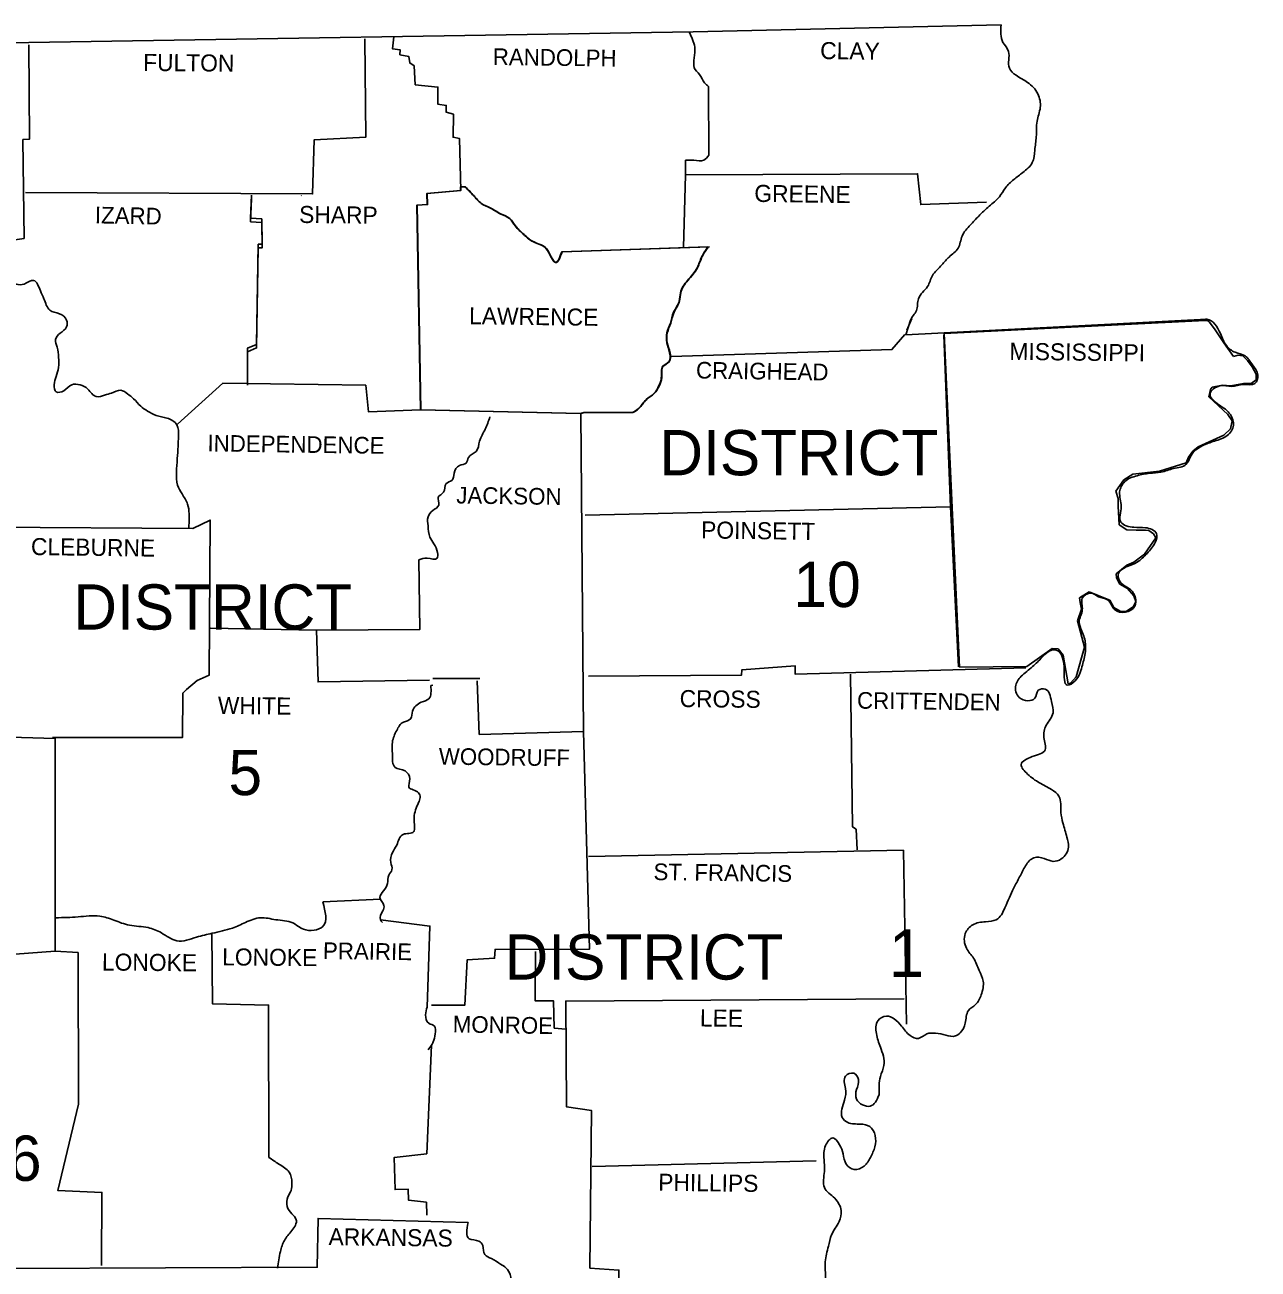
# Model space of a CAD drawing. Extents: x -42408 to 34530, y -43140 to 20491.
# Drawn here: x 3155 to 4711, y -34581 to -33011 of the extents above; entities that cross this region are included whole.
import ezdxf

# ---------------------------------------------------------------- set-up
doc = ezdxf.new("R2010")
doc.units = 0
for name, color, linetype in [('1', 7, 'Continuous'), ('2', 7, 'Continuous'), ('3', 7, 'Continuous'), ('S_MISC_BOUNDARY', 7, 'Continuous')]:
    doc.layers.add(name, color=color, linetype=linetype)

msp = doc.modelspace()

# ---------------------------------------------------------------- linework, layer by layer
at = {"layer": '1'}
for p, q in [((3988.7, -33181.7), (3988.7, -33200.2)), ((3710.3, -33215.2), (3704.6, -33215.4)), ((4016.7, -33290.9), (3832.4, -33297.3)), ((3985.1, -33292.3), (3986, -33291.4)), ((3825, -33310.9), (3829.8, -33306.1)), ((4266.5, -33401.9), (4272.5, -33383.4)), ((4268, -33395.9), (4274, -33381.4)), ((4315, -33400.1), (4644.3, -33383.9)), ((4644.3, -33383.9), (4647.2, -33383.8)), ((4647.2, -33383.8), (4649.5, -33385.4)), ((4649.5, -33385.4), (4655.9, -33394.5)), ((4334.5, -33821.1), (4315, -33400.1)), ((4655.9, -33394.5), (4667.9, -33411.9)), ((4667.9, -33411.9), (4679.9, -33429.2)), ((4679.9, -33429.2), (4685.9, -33427.5)), ((4685.9, -33427.5), (4692, -33428.6)), ((4692, -33428.6), (4697.6, -33434.2)), ((4697.6, -33434.2), (4703.8, -33442.5)), ((4703.8, -33442.5), (4708.6, -33451.8)), ((4708.6, -33451.8), (4708.7, -33458.8)), ((4653.2, -33468.1), (4651.1, -33471)), ((4666, -33465.3), (4653.2, -33468.1)), ((4676.7, -33466.5), (4666, -33465.3)), ((4692.8, -33463.3), (4676.7, -33466.5)), ((4702.5, -33463.2), (4692.8, -33463.3)), ((4708.7, -33458.8), (4702.5, -33463.2)), ((4651.1, -33471), (4648.8, -33480.2)), ((4648.8, -33480.2), (4672.8, -33502.5)), ((4672.8, -33502.5), (4678.4, -33510.7)), ((4678.4, -33510.7), (4676.2, -33520.4)), ((4668, -33528.6), (4635.4, -33543.1)), ((4676.2, -33520.4), (4668, -33528.6)), ((4635.4, -33543.1), (4628.9, -33548.6)), ((4623.1, -33556.2), (4620.5, -33563.5)), ((4628.9, -33548.6), (4623.1, -33556.2)), ((4552.9, -33577.8), (4541.5, -33585.1)), ((4586.5, -33574.2), (4552.9, -33577.8)), ((4620.5, -33563.5), (4586.5, -33574.2)), ((4541.5, -33585.1), (4531.6, -33599.2)), ((4531.6, -33599.2), (4534.7, -33608.3)), ((4534.7, -33608.3), (4534.7, -33618)), ((4534.7, -33618), (4535.6, -33641.9)), ((4535.6, -33641.9), (4545.6, -33647.9)), ((4545.6, -33647.9), (4557.4, -33648.3)), ((4557.4, -33648.3), (4569.1, -33648.6)), ((4569.1, -33648.6), (4573.4, -33648.8)), ((4573.4, -33648.8), (4578.9, -33652.9)), ((4578.9, -33652.9), (4582.2, -33658.3)), ((4582.2, -33658.3), (4567.8, -33678.8)), ((4567.8, -33678.8), (4554.3, -33689)), ((4545.5, -33692.7), (4532.1, -33703.6)), ((4532.1, -33703.6), (4532.5, -33708.7)), ((4554.3, -33689), (4545.5, -33692.7)), ((4532.5, -33708.7), (4536.7, -33716.6)), ((4536.7, -33716.6), (4546.5, -33722)), ((4497.8, -33726.2), (4485.9, -33733.9)), ((4485.9, -33733.9), (4486.5, -33739.7)), ((4509.2, -33730.9), (4497.8, -33726.2)), ((4524, -33736.9), (4509.2, -33730.9)), ((4546.5, -33722), (4554.1, -33731.2)), ((4554.1, -33731.2), (4556.7, -33738.4)), ((4488.2, -33748.2), (4483.2, -33762.7)), ((4486.5, -33739.7), (4488.2, -33748.2)), ((4528.9, -33745.9), (4524, -33736.9)), ((4537.7, -33750.9), (4528.9, -33745.9)), ((4544.9, -33750.6), (4537.7, -33750.9)), ((4553.8, -33744.8), (4544.9, -33750.6)), ((4556.7, -33738.4), (4553.8, -33744.8)), ((4483.2, -33762.7), (4492, -33796)), ((4451.3, -33797.6), (4419.2, -33820.5)), ((4458.6, -33798.1), (4451.3, -33797.6)), ((4465.1, -33806.2), (4458.6, -33798.1)), ((4492, -33796), (4481.5, -33833.4)), ((4471.3, -33842.5), (4465.1, -33806.2)), ((4419.2, -33820.5), (4334.5, -33821.1)), ((3669.7, -33835.5), (3729.3, -33835.5)), ((4474.2, -33841.5), (4471.3, -33842.5)), ((4481.5, -33833.4), (4474.2, -33841.5))]:
    msp.add_line(p, q, dxfattribs=at)
for points in [[(1640, -33034), (2449.6, -33034.5), (3160, -33033), (3998.2, -33019.9), (4386.7, -33010.9)], [(3584.1, -33028.4), (3585.1, -33152.6), (3520, -33156.1), (3518, -33224.2), (3156, -33222.2)], [(3620.6, -33025.8), (3618.7, -33041), (3628.7, -33042.5), (3628.2, -33048.5), (3639.7, -33051), (3640.7, -33059), (3646.2, -33062.5), (3647.7, -33086.5), (3676.2, -33089.5), (3676.2, -33111.1), (3686.7, -33112.6), (3686.7, -33121.1), (3695.8, -33123.6), (3695.3, -33152.6), (3703.3, -33154.1), (3705.3, -33219.7), (3662.7, -33223.7), (3663.2, -33237.7), (3650.2, -33238.2), (3654.7, -33496.6), (3856.5, -33501.1), (3860, -33902.6), (3728.3, -33906.1), (3725.8, -33838.5)], [(3160, -33036), (3161, -33155.1), (3152.5, -33155.6), (3154, -33280.3), (3119, -33285.3), (3122, -33318.8), (3134, -33334.4), (3133, -33373.9), (3064.9, -33376.4), (3062.4, -33437.5), (3000.3, -33439.5), (2997.3, -33513.6), (3000.8, -33519.6), (3002.3, -33637.8), (3109.5, -33644.8), (3108, -33908.6), (3193.1, -33911.1), (3193.1, -34179.5), (3126, -34184.5), (3121, -34243.6), (3008.3, -34244.1)], [(4017.7, -33088.5), (4018.2, -33175.1)], [(3986, -33291.9), (3988.7, -33200.2), (3988.7, -33200.2), (4281.5, -33198.7), (4285.5, -33237.7), (4368.2, -33234.7)], [(3704.6, -33215.4), (3704.8, -33219.7), (3662.2, -33223.7), (3662.7, -33237.7), (3649.7, -33238.2), (3654.2, -33496.6), (3856, -33501.1)], [(3440.9, -33225.7), (3439.9, -33254.7), (3453.9, -33255.8), (3454.4, -33287.8), (3449.4, -33287.8), (3447.4, -33414), (3435.9, -33419), (3435.9, -33461)], [(3440.9, -33230.2), (3439.9, -33259.3), (3453.9, -33260.3), (3454.4, -33292.3), (3449.4, -33292.3), (3447.4, -33418.5), (3435.9, -33423.5), (3435.9, -33465.5)], [(3503.5, -33226.7), (3504, -33226.2)], [(3832.9, -33297.3), (4018.7, -33290.8)], [(4016.7, -33291.3), (4016.7, -33290.9)], [(4266.5, -33401.9), (4646.5, -33382.4)], [(3971.1, -33429.5), (4249, -33420.5), (4265.5, -33401.4)], [(4314.6, -33402.4), (4323.1, -33619.2), (4333.1, -33821)], [(3347.8, -33514.6), (3404.9, -33463), (3585.1, -33465.5), (3588.6, -33499.1), (3654.2, -33496.6)], [(3856, -33501.1), (3860.5, -33500.1), (3921.6, -33500.1)], [(3922.1, -33500.1), (3861, -33500.1), (3856.5, -33501.1)], [(4323.1, -33619.2), (3862, -33629.7)], [(3109.5, -33644.8), (3366.8, -33646.3), (3388.9, -33635.8), (3387.4, -33831.5), (3372.3, -33838), (3358.8, -33849.5), (3354.3, -33854), (3353.8, -33910.1), (3190.1, -33910.1)], [(3652.2, -33685.8), (3653.2, -33773.9), (3523, -33774.4), (3389.4, -33771.9)], [(3523, -33774.4), (3525, -33840), (3665.7, -33837.5)], [(3866, -33832.5), (4059.2, -33831.5), (4059.7, -33824.5), (4126.8, -33819.5), (4126.8, -33830), (4418.2, -33822)], [(4196.9, -33830), (4199.4, -34022.8), (4203.9, -34025.8), (4205.4, -34051.8)], [(3669.7, -33844), (3667.2, -33844.5)], [(3860, -33902.6), (3867.5, -34177), (3748.3, -34177.5), (3747.8, -34188.5), (3713.3, -34190.5), (3710.3, -34247.6), (3668.2, -34247.6)], [(3866, -34060.3), (4263.5, -34052.3)], [(4263.5, -34052.3), (4267.5, -34271.6)], [(3531, -34117.4), (3603.6, -34113.9)], [(3603.6, -34139.9), (3666.2, -34147.9), (3662.7, -34250.1)], [(3390.9, -34156.5), (3391.9, -34246.1), (3462.5, -34247.6), (3463, -34439.8)], [(3193.1, -34179.5), (3222.1, -34181.5), (3222.6, -34372.7), (3196.6, -34481.4), (3252.2, -34483.9), (3251.7, -34576)], [(3799.4, -34180), (3798.9, -34242.1), (3821.9, -34242.1), (3822.9, -34276.6), (3837.5, -34278.1)], [(3866, -34686.2), (3905, -34683.7), (3904.5, -34582), (3868, -34579.5), (3870, -34380.8), (3838.5, -34376.2), (3837.5, -34242.6), (4264.5, -34239.6)], [(3668.2, -34298.1), (3662.2, -34435.3), (3621.2, -34439.8), (3622.2, -34480.4), (3638.7, -34479.9), (3639.2, -34493.9), (3661.7, -34496.4), (3662.2, -34512.9)], [(3871, -34451.3), (4153.4, -34444.3)], [(3714.3, -34521.9), (3525, -34516.9), (3524, -34578.5), (3141, -34580)]]:
    msp.add_lwpolyline(points, dxfattribs=at)
for points in [[(4386.7, -33010.9), (4389.2, -33033), (4396.2, -33044.5), (4397.2, -33065.5), (4405.7, -33074.5), (4420.2, -33083.5), (4433.2, -33098), (4436.2, -33115.1), (4432.2, -33132.6), (4431.2, -33152.1), (4429.2, -33169.1), (4426.2, -33184.7), (4414.2, -33197.2), (4402.7, -33206.2), (4392.2, -33216.7), (4384.7, -33227.7), (4371.7, -33239.7), (4358.6, -33252.2), (4348.1, -33263.3), (4337.6, -33277.3), (4332.6, -33292.8), (4321.1, -33303.8), (4312.1, -33313.8), (4300.1, -33327.3), (4294.1, -33340.9), (4282.5, -33356.4), (4280, -33371.4), (4272.5, -33383.4), (4272, -33385.4)], [(3993.3, -33020), (4000.2, -33039), (3999.7, -33052.5), (3999.7, -33065), (4006.2, -33073.5), (4012.7, -33084), (4017.7, -33088.5)], [(4018.2, -33175.1), (4011.7, -33181.7), (3999.2, -33181.7), (3988.7, -33181.7)], [(3832.4, -33297.3), (3824.4, -33310.8), (3816.9, -33300.3), (3811.4, -33291.8), (3794.9, -33283.8), (3784.4, -33275.3), (3773.9, -33264.8), (3766.4, -33255.2), (3754.8, -33249.2), (3741.8, -33241.7), (3730.8, -33236.2), (3721.3, -33226.7), (3710.3, -33215.2)], [(3710.8, -33215.2), (3721.8, -33226.7), (3731.3, -33236.2), (3742.3, -33241.7), (3755.3, -33249.2), (3766.9, -33255.2), (3774.4, -33264.8), (3784.9, -33275.3), (3795.4, -33283.8), (3811.9, -33291.8), (3817.4, -33300.3), (3824.9, -33310.8), (3832.9, -33297.3)], [(3921.6, -33500.1), (3929.1, -33495.1), (3939.1, -33483.6), (3948.6, -33476), (3955.1, -33466), (3958.1, -33456), (3960.1, -33441.5), (3967.6, -33436), (3968.6, -33424.5), (3965.1, -33412), (3965.1, -33399.4), (3969.6, -33387.4), (3973.6, -33373.4), (3980.6, -33359.4), (3982.1, -33348.9), (3991.2, -33333.4), (4003.2, -33317.3), (4009.2, -33303.3), (4016.7, -33291.3)], [(4017.2, -33291.3), (4009.7, -33303.3), (4003.7, -33317.3), (3991.7, -33333.4), (3982.6, -33348.9), (3981.1, -33359.4), (3974.1, -33373.4), (3970.1, -33387.4), (3965.6, -33399.4), (3965.6, -33412), (3969.1, -33424.5), (3968.1, -33436), (3960.6, -33441.5), (3958.6, -33456), (3955.6, -33466), (3949.1, -33476), (3939.6, -33483.6), (3929.6, -33495.1), (3922.1, -33500.1)], [(3134, -33334.4), (3154, -33337.9), (3166.1, -33333.4), (3174.6, -33346.4), (3179.1, -33356.4), (3186.6, -33370.9), (3198.6, -33375.4), (3207.6, -33383.4), (3207.6, -33391.9), (3199.6, -33399.9), (3193.6, -33408), (3195.6, -33417.5), (3197.6, -33430.5), (3197.6, -33443), (3194.6, -33454.5), (3192.1, -33465), (3194.6, -33474), (3204.1, -33472.5), (3214.1, -33465), (3224.6, -33465), (3234.6, -33470.5), (3245.2, -33480), (3255.7, -33478), (3264.2, -33475.5), (3276.2, -33472), (3284.7, -33476.5), (3292.2, -33482.6), (3301.2, -33492.1), (3309.7, -33498.1), (3320.8, -33503.6), (3334.3, -33507.1), (3346.8, -33515.6), (3348.8, -33530.1), (3348.3, -33542.6), (3347.3, -33558.2), (3346.3, -33575.2), (3347.8, -33591.7), (3353.3, -33602.7), (3360.3, -33615.7), (3362.3, -33627.7), (3361.8, -33646.8)], [(4641, -33382.9), (4646.5, -33382.4), (4663.6, -33400.4), (4671.1, -33415.5), (4682.1, -33424), (4694.6, -33428.5), (4704.1, -33440), (4710.6, -33452.5), (4707.1, -33463.5), (4693.1, -33464.5), (4677.6, -33467), (4662.6, -33466.5), (4650.5, -33476.5), (4661.6, -33490.1), (4676.1, -33502.6), (4680.1, -33516.1), (4672.1, -33529.1), (4656, -33536.1), (4640.5, -33542.1), (4626.5, -33554.1), (4620, -33565.7), (4604.5, -33570.7), (4588.5, -33575.2), (4574.4, -33576.7), (4558.4, -33579.7), (4542.9, -33587.2), (4536.4, -33600.2), (4538.4, -33618.7), (4537.9, -33638.3), (4554.4, -33644.8), (4568.9, -33645.3), (4582.9, -33652.8), (4581.4, -33663.8), (4570.9, -33677.8), (4558.4, -33688.8), (4545.9, -33694.3), (4534.4, -33704.8), (4538.4, -33715.4), (4548.9, -33722.4), (4556.4, -33733.9), (4555.4, -33744.4), (4543.4, -33751.9), (4530.4, -33748.9), (4520.9, -33736.4), (4509.8, -33732.4), (4500.3, -33727.9), (4489.3, -33734.4), (4489.3, -33748.9), (4485.3, -33764.4), (4488.8, -33775.9), (4493.3, -33792), (4492.8, -33804), (4488.8, -33821), (4480.3, -33838.5), (4470.3, -33844), (4466.3, -33825), (4464.3, -33809.5), (4458.3, -33800.5), (4450.3, -33800), (4439.8, -33807.5), (4428.2, -33819), (4413.7, -33831.5), (4405.2, -33844), (4409.7, -33859.6), (4420.7, -33863.6), (4429.2, -33860.6), (4433.7, -33850.5), (4442.3, -33849), (4450.3, -33864.6)], [(3741.8, -33505.6), (3735.8, -33521.1), (3728.8, -33536.1), (3724.3, -33549.1), (3714.8, -33556.7), (3711.8, -33563.7), (3703.3, -33566.7), (3696.8, -33576.7), (3693.8, -33585.7), (3686.7, -33589.7), (3683.2, -33600.7), (3676.7, -33606.7), (3677.2, -33616.7), (3669.7, -33623.7), (3663.7, -33631.8), (3663.7, -33642.8), (3666.2, -33657.3), (3671.2, -33665.8), (3675.7, -33676.8), (3675.2, -33683.8), (3662.7, -33683.8), (3652.2, -33685.8)], [(3667.2, -33844.5), (3664.7, -33861.1), (3655.2, -33865.6), (3644.2, -33876.6), (3641.7, -33886.6), (3632.7, -33890.6), (3624.2, -33901.1), (3618.7, -33915.6), (3618.7, -33930.7), (3622.2, -33947.7), (3634.7, -33952.2), (3640.7, -33962.2), (3639.7, -33972.7), (3651.7, -33979.7), (3653.7, -33985.7), (3651.7, -33992.2), (3646.2, -34010.8), (3646.7, -34023.3), (3645.7, -34028.8), (3632.2, -34032.3), (3624.2, -34045.8), (3618.7, -34055.3), (3616.7, -34067.8), (3618.2, -34076.8), (3614.2, -34083.9), (3612.7, -34094.4), (3607.6, -34103.4), (3603.1, -34111.9), (3608.1, -34121.9), (3606.6, -34128.9), (3603.6, -34139.9), (3606.1, -34143.4)], [(4450.3, -33864.6), (4452.3, -33879.1), (4443.8, -33894.6), (4440.8, -33910.1), (4442.3, -33925.6), (4426.2, -33934.2), (4412.2, -33944.2), (4420.2, -33956.2), (4435.2, -33967.2), (4450.3, -33975.7), (4459.8, -33984.2), (4462.3, -34004.7), (4464.8, -34017.8), (4469.8, -34035.8), (4471.8, -34048.3), (4462.8, -34063.3), (4452.3, -34066.3), (4441.3, -34062.8), (4428.2, -34061.8), (4417.7, -34071.8), (4410.2, -34085.9), (4402.7, -34099.9), (4397.2, -34111.9), (4391.7, -34124.9), (4380.7, -34139.9), (4367.2, -34142.4), (4351.1, -34146.4), (4341.6, -34157.5), (4343.1, -34176), (4352.1, -34188.5), (4359.1, -34204), (4364.2, -34217.5), (4361.7, -34234.6), (4354.6, -34247.1), (4345.6, -34254.6), (4341.6, -34270.6), (4335.1, -34282.6), (4329.1, -34286.6), (4317.1, -34285.6), (4304.1, -34283.1), (4293.1, -34284.1), (4282.5, -34289.6), (4272, -34286.1), (4261, -34274.1), (4252, -34265.1), (4242, -34261.6), (4231.5, -34267.1), (4229.5, -34283.6), (4234.5, -34300.6), (4239, -34323.7), (4234.5, -34337.7), (4233, -34360.7)], [(3194.1, -34137.4), (3222.1, -34136.4), (3249.7, -34135.4), (3267.2, -34140.4), (3287.2, -34146.9), (3310.7, -34149.9), (3327.3, -34156.5), (3346.8, -34166.5), (3371.8, -34162), (3391.4, -34157), (3416.9, -34150.4), (3433.4, -34143.4), (3452.4, -34137.4), (3471.5, -34139.9), (3493, -34143.9), (3506.5, -34151.9), (3531, -34148.4), (3531, -34117.4)], [(3662.7, -34250.1), (3660.7, -34260.1), (3664.7, -34270.6), (3671.7, -34274.1), (3672.7, -34284.1), (3670.2, -34294.1), (3668.2, -34298.1), (3663.7, -34304.1)], [(4233, -34360.7), (4221.5, -34375.2), (4204.4, -34366.2), (4204.4, -34354.2), (4206.9, -34341.7), (4200.9, -34333.7), (4190.4, -34337.2), (4190.4, -34352.7), (4189.4, -34367.7), (4186.4, -34389.3), (4193.4, -34395.8), (4209.4, -34397.8), (4221, -34400.8), (4228, -34412.3), (4227.5, -34426.3), (4222, -34439.8), (4214, -34450.8), (4201.4, -34454.9), (4191.4, -34448.3), (4187.4, -34435.3), (4182.9, -34423.8), (4174.4, -34415.3), (4165.4, -34424.8), (4163.4, -34442.3), (4163.9, -34457.4), (4163.9, -34477.9), (4176.9, -34491.4), (4184.9, -34506.9), (4182.4, -34520.9), (4172.9, -34537.5), (4168.9, -34552), (4164.9, -34571.5), (4165.4, -34593), (4161.9, -34614.1), (4154.9, -34628.1), (4141.9, -34639.6), (4133.3, -34647.1), (4126.3, -34654.6), (4122.8, -34669.6), (4120.3, -34680.2), (4110.8, -34692.7), (4103.3, -34693.7), (4097.3, -34688.7), (4095.3, -34680.2), (4095.3, -34671.6), (4091.3, -34663.1), (4078.8, -34659.6), (4068.8, -34660.1), (4064.3, -34667.1), (4070.8, -34686.7), (4073.3, -34699.2), (4069.8, -34716.2), (4071.8, -34718.2), (4053.7, -34727.7), (4039.2, -34729.2), (4027.2, -34732.7), (4015.7, -34740.2), (4010.2, -34751.2), (4002.2, -34760.3), (3995.2, -34768.8), (3985.6, -34772.8), (3975.1, -34770.8), (3961.1, -34769.3), (3953.1, -34779.3), (3955.6, -34793.8), (3965.1, -34802.3), (3979.1, -34806.3), (3993.7, -34805.3), (4007.7, -34803.8), (4020.7, -34810.8), (4018.2, -34824.3), (4005.7, -34830.9), (3987.2, -34832.9), (3972.1, -34831.4), (3954.1, -34835.4), (3945.1, -34846.9), (3950.1, -34864.4), (3969.6, -34871.4), (3978.6, -34887.9), (3979.1, -34903.4), (3972.6, -34924), (3963.6, -34933.5), (3946.1, -34937.5), (3932.6, -34940), (3930.6, -34963), (3924.6, -34974.5), (3914.1, -34978), (3899, -34970.5), (3890, -34967), (3879, -34962), (3865, -34953.5), (3854.5, -34955), (3857.5, -34977), (3858.5, -34978), (3870.5, -34994.6), (3882.5, -35007.6), (3888, -35023.1)], [(3463, -34439.8), (3475.5, -34448.3), (3488.5, -34458.4), (3492, -34471.9), (3491, -34481.4), (3487, -34489.4), (3486, -34501.9), (3492, -34510.9), (3497.5, -34518.4), (3492, -34532), (3482.5, -34544.5), (3477.5, -34558.5), (3474, -34579.5)], [(3714.3, -34521.9), (3715.8, -34542.5), (3727.8, -34545.5), (3732.8, -34551), (3735.3, -34562.5), (3743.8, -34567.5), (3755.3, -34574.5), (3762.4, -34579.5), (3767.4, -34587.5), (3770.4, -34600.5), (3778.4, -34609.1), (3789.4, -34613.1), (3797.4, -34622.6), (3802.4, -34636.1), (3810.4, -34642.1), (3818.4, -34652.6), (3822.4, -34657.1), (3829.4, -34669.1), (3836.4, -34675.1), (3841.5, -34678.6), (3849.5, -34681.2), (3859.5, -34687.7), (3866, -34697.7), (3866, -34705.2), (3863.5, -34716.7), (3861.5, -34728.7), (3860.5, -34742.2), (3859.5, -34754.2), (3864, -34764.3), (3861.5, -34779.3), (3856.5, -34787.3), (3856, -34798.3), (3854.5, -34814.8), (3852.5, -34824.3), (3848, -34839.9), (3841.5, -34847.9)]]:
    msp.add_spline(points, degree=3, dxfattribs=at)
at = {"layer": 'S_MISC_BOUNDARY'}
msp.add_line((3710.8, -33215.2), (3705.1, -33215.4), dxfattribs=at)

# ---------------------------------------------------------------- texts
at = {"layer": '1'}
msp.add_text('1', height=60.1, dxfattribs=at).set_placement((4245, -34212))
at = {"layer": '2'}
for s, height, rotation, p in [('RANDOLPH', 21.03, 359.2583, (3745.3, -33061.5)), ('CLAY', 21.52, 359.2258, (4158.4, -33054)), ('FULTON', 21.52, 359.4996, (3304.2, -33069)), ('GREENE', 21.53, 359.2361, (4075.3, -33234.2)), ('IZARD', 21.02, 358.9258, (3243.2, -33261.3)), ('SHARP', 21.52, 359.3905, (3501, -33260.8)), ('LAWRENCE', 21.53, 359.2678, (3715.4, -33388.6)), ('MISSISSIPPI', 21.524, 359.3097, (4397.2, -33433.5)), ('CRAIGHEAD', 21.03, 359.1159, (4001.7, -33457)), ('INDEPENDENCE', 21.022, 359.2187, (3385.3, -33549.1)), ('JACKSON', 21.02, 359.1352, (3699.3, -33614.7)), ('POINSETT', 21.52, 359.1987, (4008.2, -33658.8)), ('CLEBURNE', 21.52, 359.2535, (3162.6, -33679.8)), ('WHITE', 21.53, 359.3139, (3398.4, -33880.1)), ('CROSS', 21.52, 359.3839, (3981.1, -33871.6)), ('CRITTENDEN', 21.03, 359.213, (4204.9, -33873.6)), ('WOODRUFF', 21.02, 359.2748, (3677.2, -33944.2)), ('ST. FRANCIS', 21.022, 359.2216, (3948.1, -34089.9)), ('PRAIRIE', 21.03, 359.2116, (3531, -34189.5)), ('LONOKE', 21.53, 359.4974, (3252.2, -34204)), ('LONOKE', 21.53, 359.4974, (3403.9, -34197.5)), ('LEE', 21.53, 359.4327, (4006.7, -34274.6)), ('MONROE', 21.02, 359.0331, (3694.8, -34282.1)), ('PHILLIPS', 21.52, 359.3179, (3954.1, -34481.9)), ('ARKANSAS', 21.52, 359.2678, (3538.1, -34550.5))]:
    msp.add_text(s, height=height, rotation=rotation, dxfattribs=at).set_placement(p)
at = {"layer": '3'}
for s, height, p in [('DISTRICT', 57.08, (3955.6, -33579.2)), ('10', 57.08, (4124.8, -33745.4)), ('DISTRICT', 57.08, (3216.1, -33773.9)), ('5', 57.1, (3411.9, -33982.7)), ('DISTRICT', 57.08, (3760.3, -34215.5)), ('DISTRICT 6', 57.08, (2760.5, -34469.4))]:
    msp.add_text(s, height=height, dxfattribs=at).set_placement(p)

doc.saveas('drawing.dxf')
